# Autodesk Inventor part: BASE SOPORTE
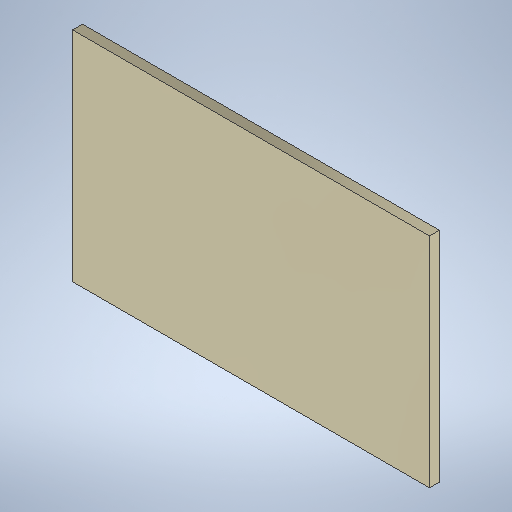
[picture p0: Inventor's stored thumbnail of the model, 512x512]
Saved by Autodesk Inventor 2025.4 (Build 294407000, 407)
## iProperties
Created: 2026-06
Part Number: BASE SOPORTE
Material: Generic
Document SubType Name: Modeling
Designer: Marcio Valenzuela
Density: 1 g/cm^3
Appearance: Default
Author: Marcio Valenzuela
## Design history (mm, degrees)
sketch "Sketch1"
  geometry: L1 (-90, 55)-(90, 55); L2 (90, 55)-(90, -55); L3 (90, -55)-(-90, -55); L4 (-90, -55)-(-90, 55); L5 (-90, 55)-(90, -55); L6 (90, 55)-(-90, -55); 1 further point
  constraints: 12 end point, 2 midpoint, 2 parallel, 1 horizontal, 1 perpendicular
  dimensions: "d4" = 180 distance of L1.start L1.end; "d5" = 110 distance of L3.end L1.start
extrude "Extrusion1" new body sketch "Sketch1" distance "d2" = 5; taper "d3" = 0 deg
body "Solid1"
